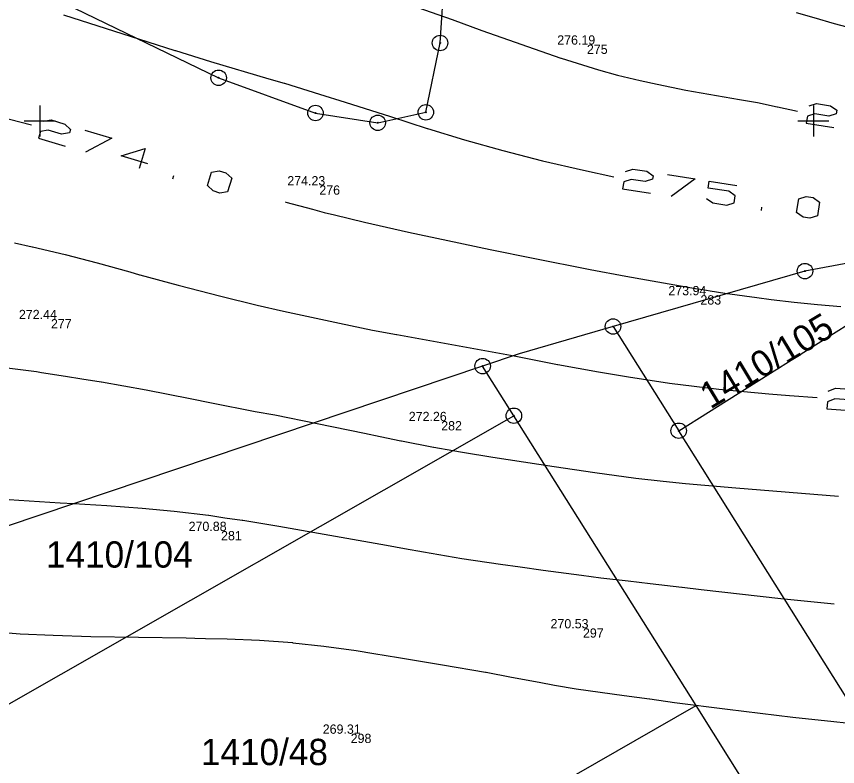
# Model space of a CAD drawing. Extents: x -771260 to -770828, y -1053564 to -1052811.
# Drawn here: x -771201.5 to -771148.4, y -1053191.7 to -1053143.2 of the extents above; entities that cross this region are included whole.
import ezdxf

# ---------------------------------------------------------------- set-up
doc = ezdxf.new("R2010")
doc.units = 0
for name, color, linetype in [('14_8_2023_krizky', 7, 'Continuous'), ('25_3_2019_krizky_JTSK', 7, 'Continuous'), ('25_3_2019_vrstevnice_interval_po_1m', 7, 'Continuous'), ('25_3_2019_zamereny_bod', 7, 'Continuous'), ('25_3_2019_zamereny_bod_cislo', 7, 'Continuous'), ('25_3_2019_zamereny_bod_vyska', 7, 'Continuous'), ('Default', 7, 'Continuous'), ('DKM_Hranice parcel', 7, 'Continuous'), ('DKM_Parcelní čísla', 7, 'Continuous'), ('DKM_Značky bodu BP', 7, 'Continuous')]:
    doc.layers.add(name, color=color, linetype=linetype)

# ---------------------------------------------------------------- blocks, each defined once
blk = doc.blocks.new('POINT_DISPLAY')
at = {"layer": 'Default'}
blk.add_line((0, 0), (0, 0), dxfattribs=at)
blk = doc.blocks.new('KRIZEK')
at = {"layer": '25_3_2019_krizky_JTSK'}
for p, q in [((0, 10), (0, -10)), ((-10, 0), (10, 0))]:
    blk.add_line(p, q, dxfattribs=at)

msp = doc.modelspace()

# ---------------------------------------------------------------- linework, layer by layer
at = {"layer": '25_3_2019_vrstevnice_interval_po_1m'}
for points in [[(-771176.495, -1053142.335), (-771173.356, -1053143.447), (-771171.429, -1053144.145), (-771166.321, -1053145.933), (-771166.299, -1053145.94), (-771163.9, -1053146.699), (-771163.882, -1053146.705), (-771162.655, -1053147.03), (-771161.203, -1053147.394), (-771160.11, -1053147.627), (-771158.237, -1053148), (-771154.77, -1053148.605), (-771153.622, -1053148.815), (-771152.336, -1053149.082), (-771152.333, -1053149.082), (-771151.031, -1053149.364)], [(-771198.459, -1053143.131), (-771193.008, -1053144.884), (-771191.261, -1053145.439), (-771191.218, -1053145.452), (-771188.954, -1053146.148), (-771185.193, -1053147.279), (-771184.207, -1053147.564), (-771184.193, -1053147.568), (-771181.911, -1053148.263), (-771180.257, -1053148.792), (-771177.326, -1053149.711), (-771174.969, -1053150.485), (-771174.946, -1053150.492), (-771172.54, -1053151.23), (-771170.074, -1053151.921), (-771167.509, -1053152.578), (-771164.865, -1053153.193), (-771162.899, -1053153.607)], [(-771151.125, -1053142.985), (-771149.981, -1053143.315), (-771148.658, -1053143.697), (-771147.434, -1053144.028), (-771144.859, -1053144.682), (-771143.67, -1053144.965), (-771143.652, -1053144.97), (-771142.265, -1053145.32), (-771139.641, -1053145.912), (-771138.851, -1053146.062), (-771138.315, -1053146.174), (-771136.98, -1053146.418), (-771136.977, -1053146.419), (-771135.671, -1053146.639), (-771134.241, -1053146.845)], [(-771173.356, -1053143.447), (-771173.356, -1053143.447)], [(-771148.658, -1053143.697), (-771148.658, -1053143.697)], [(-771171.429, -1053144.145), (-771171.429, -1053144.145)], [(-771193.008, -1053144.884), (-771193.008, -1053144.884)], [(-771191.218, -1053145.452), (-771191.218, -1053145.452)], [(-771166.321, -1053145.933), (-771166.321, -1053145.933)], [(-771188.954, -1053146.148), (-771188.954, -1053146.148)], [(-771163.882, -1053146.705), (-771163.882, -1053146.705)], [(-771162.655, -1053147.03), (-771162.655, -1053147.03)], [(-771185.193, -1053147.279), (-771185.193, -1053147.279)], [(-771184.193, -1053147.568), (-771184.193, -1053147.568)], [(-771161.203, -1053147.394), (-771161.203, -1053147.394)], [(-771160.11, -1053147.627), (-771160.11, -1053147.627)], [(-771158.237, -1053148), (-771158.237, -1053148)], [(-771181.911, -1053148.263), (-771181.911, -1053148.263)], [(-771154.77, -1053148.605), (-771154.77, -1053148.605)], [(-771180.257, -1053148.792), (-771180.257, -1053148.792)], [(-771153.622, -1053148.815), (-771153.622, -1053148.815)], [(-771152.336, -1053149.082), (-771152.336, -1053149.082)], [(-771150.287, -1053149.024), (-771149.803, -1053148.872), (-771148.906, -1053149.016), (-771148.494, -1053149.312), (-771148.53, -1053149.536), (-771149.014, -1053149.688), (-771149.91, -1053149.544), (-771150.395, -1053149.696), (-771150.467, -1053150.144), (-771148.674, -1053150.432)], [(-771202.635, -1053149.719), (-771200.54, -1053150.257)], [(-771199.757, -1053150.02), (-771199.256, -1053149.934), (-771198.388, -1053150.198), (-771198.019, -1053150.547), (-771198.085, -1053150.764), (-771198.585, -1053150.849), (-771199.454, -1053150.586), (-771199.954, -1053150.672), (-771200.086, -1053151.106), (-771198.348, -1053151.632)], [(-771177.326, -1053149.711), (-771177.326, -1053149.711)], [(-771197.085, -1053150.593), (-771195.347, -1053151.119), (-771197.045, -1053152.027)], [(-771174.969, -1053150.485), (-771174.969, -1053150.485)], [(-771172.54, -1053151.23), (-771172.54, -1053151.23)], [(-771193.004, -1053152.778), (-771194.742, -1053152.251), (-771193.176, -1053151.778), (-771193.57, -1053153.081)], [(-771170.074, -1053151.921), (-771170.074, -1053151.921)], [(-771167.509, -1053152.578), (-771167.509, -1053152.578)], [(-771188.793, -1053154.529), (-771189.161, -1053154.18), (-771188.898, -1053153.311), (-771188.398, -1053153.226), (-771187.963, -1053153.357), (-771187.595, -1053153.706), (-771187.858, -1053154.575), (-771188.358, -1053154.66), (-771188.793, -1053154.529)], [(-771164.865, -1053153.193), (-771164.865, -1053153.193)], [(-771162.156, -1053153.265), (-771161.672, -1053153.111), (-771160.775, -1053153.253), (-771160.362, -1053153.547), (-771160.398, -1053153.772), (-771160.881, -1053153.925), (-771161.778, -1053153.784), (-771162.262, -1053153.937), (-771162.332, -1053154.386), (-771160.539, -1053154.668)], [(-771191.399, -1053153.739), (-771191.333, -1053153.522)], [(-771159.43, -1053153.465), (-771157.637, -1053153.747), (-771159.194, -1053154.88)], [(-771156.917, -1053155.009), (-771156.504, -1053155.304), (-771155.607, -1053155.445), (-771155.124, -1053155.292), (-771155.053, -1053154.844), (-771155.466, -1053154.549), (-771156.811, -1053154.337), (-771156.74, -1053153.888), (-771154.947, -1053154.171)], [(-771150.675, -1053156.223), (-771151.088, -1053155.928), (-771150.947, -1053155.031), (-771150.464, -1053154.877), (-771150.015, -1053154.948), (-771149.602, -1053155.243), (-771149.743, -1053156.14), (-771150.227, -1053156.293), (-771150.675, -1053156.223)], [(-771184.111, -1053155.236), (-771184.111, -1053155.236)], [(-771184.111, -1053155.236), (-771184.086, -1053155.243), (-771182.368, -1053155.706), (-771181.615, -1053155.909), (-771180.948, -1053156.07), (-771179.002, -1053156.54), (-771176.166, -1053157.182), (-771173.622, -1053157.74), (-771170.887, -1053158.318), (-771168.122, -1053158.88), (-771164.439, -1053159.597), (-771162.119, -1053160.03), (-771160.792, -1053160.264), (-771157.495, -1053160.846), (-771157.479, -1053160.849), (-771157.152, -1053160.901), (-771156.683, -1053160.975), (-771155.723, -1053161.128), (-771153.65, -1053161.425), (-771152.741, -1053161.538), (-771151.241, -1053161.708), (-771149.737, -1053161.858), (-771148.227, -1053161.991)], [(-771181.615, -1053155.909), (-771181.615, -1053155.909)], [(-771153.365, -1053155.799), (-771153.33, -1053155.574)], [(-771179.002, -1053156.54), (-771179.002, -1053156.54)], [(-771176.166, -1053157.182), (-771176.166, -1053157.182)], [(-771201.627, -1053157.886), (-771200.482, -1053158.129), (-771200.47, -1053158.132), (-771198.357, -1053158.641), (-771196.286, -1053159.182), (-771194.18, -1053159.761), (-771193.55, -1053159.942), (-771193.525, -1053159.948), (-771191.056, -1053160.616), (-771188.304, -1053161.329), (-771185.955, -1053161.909), (-771184.242, -1053162.296), (-771184.241, -1053162.297), (-771180.621, -1053163.082), (-771178.486, -1053163.517), (-771176.95, -1053163.807), (-771176.932, -1053163.811), (-771172.176, -1053164.663), (-771169.342, -1053165.193), (-771166.539, -1053165.738), (-771166.511, -1053165.743), (-771163.882, -1053166.232), (-771161.945, -1053166.554), (-771159.308, -1053166.951), (-771159.306, -1053166.951), (-771157.713, -1053167.156), (-771156.108, -1053167.335), (-771152.88, -1053167.638), (-771151.542, -1053167.743), (-771149.761, -1053167.882)], [(-771200.47, -1053158.132), (-771200.47, -1053158.132)], [(-771173.622, -1053157.74), (-771173.622, -1053157.74)], [(-771198.357, -1053158.641), (-771198.357, -1053158.641)], [(-771170.887, -1053158.318), (-771170.887, -1053158.318)], [(-771196.286, -1053159.182), (-771196.286, -1053159.182)], [(-771168.122, -1053158.88), (-771168.122, -1053158.88)], [(-771194.18, -1053159.761), (-771194.18, -1053159.761)], [(-771164.439, -1053159.597), (-771164.439, -1053159.597)], [(-771193.55, -1053159.942), (-771193.55, -1053159.942)], [(-771162.119, -1053160.03), (-771162.119, -1053160.03)], [(-771191.056, -1053160.616), (-771191.056, -1053160.616)], [(-771188.304, -1053161.329), (-771188.304, -1053161.329)], [(-771157.479, -1053160.849), (-771157.479, -1053160.849)], [(-771155.723, -1053161.128), (-771155.723, -1053161.128)], [(-771153.65, -1053161.425), (-771153.65, -1053161.425)], [(-771152.741, -1053161.538), (-771152.741, -1053161.538)], [(-771151.241, -1053161.708), (-771151.241, -1053161.708)], [(-771149.737, -1053161.858), (-771149.737, -1053161.858)], [(-771185.955, -1053161.909), (-771185.955, -1053161.909)], [(-771184.242, -1053162.296), (-771184.242, -1053162.296)], [(-771180.621, -1053163.082), (-771180.621, -1053163.082)], [(-771178.486, -1053163.517), (-771178.486, -1053163.517)], [(-771176.932, -1053163.811), (-771176.932, -1053163.811)], [(-771172.176, -1053164.663), (-771172.176, -1053164.663)], [(-771169.342, -1053165.193), (-771169.342, -1053165.193)], [(-771202.103, -1053165.959), (-771200.206, -1053166.21), (-771199.884, -1053166.259), (-771198.331, -1053166.492), (-771197.273, -1053166.668), (-771196.025, -1053166.866), (-771195.999, -1053166.87), (-771193.114, -1053167.395), (-771190.272, -1053167.954), (-771188.908, -1053168.235), (-771186.085, -1053168.779), (-771186.084, -1053168.779), (-771184.812, -1053169.009), (-771182.065, -1053169.554), (-771179.002, -1053170.195), (-771178.004, -1053170.411), (-771176.655, -1053170.687), (-771176.627, -1053170.692), (-771174.544, -1053171.094), (-771174.543, -1053171.094), (-771173.303, -1053171.311), (-771172.685, -1053171.412), (-771170.712, -1053171.731), (-771166.762, -1053172.342), (-771164.122, -1053172.73), (-771161.472, -1053173.09), (-771161.47, -1053173.09), (-771159.722, -1053173.285), (-771158.259, -1053173.437), (-771155.025, -1053173.722), (-771148.389, -1053174.265)], [(-771166.539, -1053165.738), (-771166.539, -1053165.738)], [(-771200.206, -1053166.21), (-771200.206, -1053166.21)], [(-771198.331, -1053166.492), (-771198.331, -1053166.492)], [(-771197.273, -1053166.668), (-771197.273, -1053166.668)], [(-771163.882, -1053166.232), (-771163.882, -1053166.232)], [(-771161.945, -1053166.554), (-771161.945, -1053166.554)], [(-771195.999, -1053166.87), (-771195.999, -1053166.87)], [(-771159.308, -1053166.951), (-771159.308, -1053166.951)], [(-771157.713, -1053167.156), (-771157.713, -1053167.156)], [(-771193.114, -1053167.395), (-771193.114, -1053167.395)], [(-771156.108, -1053167.335), (-771156.108, -1053167.335)], [(-771152.88, -1053167.638), (-771152.88, -1053167.638)], [(-771149.05, -1053167.477), (-771148.581, -1053167.283), (-771147.676, -1053167.347), (-771147.239, -1053167.605), (-771147.255, -1053167.832), (-771147.724, -1053168.026), (-771148.629, -1053167.962), (-771149.098, -1053168.156), (-771149.13, -1053168.609), (-771147.319, -1053168.737)], [(-771190.272, -1053167.954), (-771190.272, -1053167.954)], [(-771188.908, -1053168.235), (-771188.908, -1053168.235)], [(-771186.085, -1053168.779), (-771186.085, -1053168.779)], [(-771184.812, -1053169.009), (-771184.812, -1053169.009)], [(-771182.065, -1053169.554), (-771182.065, -1053169.554)], [(-771179.002, -1053170.195), (-771179.002, -1053170.195)], [(-771178.004, -1053170.411), (-771178.004, -1053170.411)], [(-771176.655, -1053170.687), (-771176.655, -1053170.687)], [(-771174.544, -1053171.094), (-771174.544, -1053171.094)], [(-771173.303, -1053171.311), (-771173.303, -1053171.311)], [(-771170.712, -1053171.731), (-771170.712, -1053171.731)], [(-771166.762, -1053172.342), (-771166.762, -1053172.342)], [(-771164.122, -1053172.73), (-771164.122, -1053172.73)], [(-771161.472, -1053173.09), (-771161.472, -1053173.09)], [(-771159.722, -1053173.285), (-771159.722, -1053173.285)], [(-771158.259, -1053173.437), (-771158.259, -1053173.437)], [(-771155.025, -1053173.722), (-771155.025, -1053173.722)], [(-771202.631, -1053174.442), (-771201.343, -1053174.521), (-771198.689, -1053174.685), (-771197.802, -1053174.732), (-771195.666, -1053174.866), (-771193.386, -1053175.038), (-771191.318, -1053175.229), (-771189.102, -1053175.491), (-771189.077, -1053175.494), (-771188.038, -1053175.65), (-771188.037, -1053175.651), (-771186.908, -1053175.807), (-771186.879, -1053175.812), (-771184.542, -1053176.201), (-771177.593, -1053177.422), (-771176.436, -1053177.635), (-771175.199, -1053177.862), (-771172.713, -1053178.281), (-771170.216, -1053178.662), (-771168.963, -1053178.837), (-771167.475, -1053179.034), (-771165, -1053179.361), (-771163.745, -1053179.537), (-771163.742, -1053179.537), (-771161.984, -1053179.74), (-771160.543, -1053179.916), (-771158.515, -1053180.137), (-771158.479, -1053180.142), (-771157.253, -1053180.293), (-771152.101, -1053180.869), (-771148.661, -1053181.229)], [(-771198.689, -1053174.685), (-771198.689, -1053174.685)], [(-771197.802, -1053174.732), (-771197.802, -1053174.732)], [(-771195.666, -1053174.866), (-771195.666, -1053174.866)], [(-771193.386, -1053175.038), (-771193.386, -1053175.038)], [(-771191.318, -1053175.229), (-771191.318, -1053175.229)], [(-771189.077, -1053175.494), (-771189.077, -1053175.494)], [(-771188.038, -1053175.65), (-771188.038, -1053175.65)], [(-771186.908, -1053175.807), (-771186.908, -1053175.807)], [(-771184.542, -1053176.201), (-771184.542, -1053176.201)], [(-771177.593, -1053177.422), (-771177.593, -1053177.422)], [(-771175.199, -1053177.862), (-771175.199, -1053177.862)], [(-771172.713, -1053178.281), (-771172.713, -1053178.281)], [(-771170.216, -1053178.662), (-771170.216, -1053178.662)], [(-771168.963, -1053178.837), (-771168.963, -1053178.837)], [(-771165, -1053179.361), (-771165, -1053179.361)], [(-771163.745, -1053179.537), (-771163.745, -1053179.537)], [(-771161.984, -1053179.74), (-771161.984, -1053179.74)], [(-771160.543, -1053179.916), (-771160.543, -1053179.916)], [(-771158.515, -1053180.137), (-771158.515, -1053180.137)], [(-771157.253, -1053180.293), (-771157.253, -1053180.293)], [(-771152.101, -1053180.869), (-771152.101, -1053180.869)], [(-771202.037, -1053183.098), (-771201.274, -1053183.152), (-771199.14, -1053183.256), (-771196.692, -1053183.328), (-771190.544, -1053183.428), (-771189.972, -1053183.437), (-771189.29, -1053183.461), (-771187.893, -1053183.491), (-771185.792, -1053183.579), (-771183.67, -1053183.731), (-771183.65, -1053183.732), (-771181.632, -1053183.953), (-771179.552, -1053184.238), (-771178.402, -1053184.425), (-771176.808, -1053184.684), (-771173.981, -1053185.156), (-771171.185, -1053185.643), (-771171.155, -1053185.648), (-771169.521, -1053185.96), (-771167.727, -1053186.283), (-771166.73, -1053186.475), (-771165.335, -1053186.714), (-771165.333, -1053186.715), (-771162.225, -1053187.155), (-771160.603, -1053187.369), (-771160.575, -1053187.373), (-771158.973, -1053187.596), (-771155.552, -1053188.039), (-771151.324, -1053188.541), (-771148.69, -1053188.836), (-771147.096, -1053189.004)], [(-771201.274, -1053183.152), (-771201.274, -1053183.152)], [(-771199.14, -1053183.256), (-771199.14, -1053183.256)], [(-771196.692, -1053183.328), (-771196.692, -1053183.328)], [(-771189.972, -1053183.437), (-771189.972, -1053183.437)], [(-771189.29, -1053183.461), (-771189.29, -1053183.461)], [(-771187.893, -1053183.491), (-771187.893, -1053183.491)], [(-771185.792, -1053183.579), (-771185.792, -1053183.579)], [(-771183.65, -1053183.732), (-771183.65, -1053183.732)], [(-771181.632, -1053183.953), (-771181.632, -1053183.953)], [(-771179.552, -1053184.238), (-771179.552, -1053184.238)], [(-771176.808, -1053184.684), (-771176.808, -1053184.684)], [(-771173.981, -1053185.156), (-771173.981, -1053185.156)], [(-771171.185, -1053185.643), (-771171.185, -1053185.643)], [(-771169.521, -1053185.96), (-771169.521, -1053185.96)], [(-771167.727, -1053186.283), (-771167.727, -1053186.283)], [(-771166.73, -1053186.475), (-771166.73, -1053186.475)], [(-771165.333, -1053186.715), (-771165.333, -1053186.715)], [(-771162.225, -1053187.155), (-771162.225, -1053187.155)], [(-771160.575, -1053187.373), (-771160.575, -1053187.373)], [(-771158.973, -1053187.596), (-771158.973, -1053187.596)], [(-771155.552, -1053188.039), (-771155.552, -1053188.039)], [(-771151.324, -1053188.541), (-771151.324, -1053188.541)], [(-771148.69, -1053188.836), (-771148.69, -1053188.836)], [(-771148.69, -1053188.836), (-771148.69, -1053188.836)]]:
    msp.add_lwpolyline(points, dxfattribs=at)
at = {"layer": 'DKM_Hranice parcel'}
for p, q in [((-771158.71, -1053170.03), (-771138.1, -1053157.08)), ((-771162.95, -1053163.29), (-771158.71, -1053170.03)), ((-771169.36, -1053169.06), (-771171.38, -1053165.85)), ((-771212.03, -1053193.43), (-771169.36, -1053169.06)), ((-771157.58, -1053187.8), (-771169.36, -1053169.06)), ((-771147.01, -1053188.66), (-771158.71, -1053170.03)), ((-771200.65, -1053212.45), (-771157.58, -1053187.8)), ((-771145.98, -1053206.27), (-771157.58, -1053187.8))]:
    msp.add_line(p, q, dxfattribs=at)
for points in [[(-771234.22, -1053144), (-771211.57, -1053140.91), (-771205.43, -1053140.71), (-771198.42, -1053142.38), (-771188.44, -1053147.21), (-771182.18, -1053149.49), (-771178.16, -1053150.12), (-771175.05, -1053149.44), (-771174.13, -1053144.96), (-771173.57, -1053136.47), (-771171.38, -1053112.57), (-771169.97, -1053090.2), (-771169.61, -1053079.22)], [(-771138.1, -1053157.08), (-771142.45, -1053158.2), (-771150.55, -1053159.71), (-771162.95, -1053163.29)], [(-771162.95, -1053163.29), (-771169.02, -1053165.05), (-771171.38, -1053165.85)], [(-771171.38, -1053165.85), (-771204.36, -1053176.95), (-771217.3, -1053182.82)]]:
    msp.add_lwpolyline(points, dxfattribs=at)
at = {"layer": 'DKM_Značky bodu BP'}
for centre, radius in [((-771174.13, -1053144.96), 0.5), ((-771174.13, -1053144.96), 0.0303), ((-771188.44, -1053147.21), 0.5), ((-771188.44, -1053147.21), 0.0303), ((-771182.18, -1053149.49), 0.5), ((-771175.05, -1053149.44), 0.5), ((-771182.18, -1053149.49), 0.0303), ((-771178.16, -1053150.12), 0.5), ((-771175.05, -1053149.44), 0.0303), ((-771178.16, -1053150.12), 0.0303), ((-771150.55, -1053159.71), 0.5), ((-771150.55, -1053159.71), 0.0303), ((-771162.95, -1053163.29), 0.5), ((-771162.95, -1053163.29), 0.0303), ((-771171.38, -1053165.85), 0.5), ((-771171.38, -1053165.85), 0.0303), ((-771169.36, -1053169.06), 0.5), ((-771169.36, -1053169.06), 0.0303), ((-771158.71, -1053170.03), 0.5), ((-771158.71, -1053170.03), 0.0303)]:
    msp.add_circle(centre, radius, dxfattribs=at)

# ---------------------------------------------------------------- block references
at = {"layer": '14_8_2023_krizky', "xscale": 0.1, "yscale": 0.10000000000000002}
for p in [(-771200, -1053150), (-771150, -1053150)]:
    msp.add_blockref('KRIZEK', p, dxfattribs=at)
at = {"layer": '25_3_2019_zamereny_bod', "xscale": 0.1, "yscale": 0.10000000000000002}
for p in [(-771164.639, -1053145.066), (-771181.931, -1053154.169), (-771157.303, -1053161.27), (-771199.276, -1053162.815), (-771174.055, -1053169.408), (-771188.282, -1053176.512), (-771164.895, -1053182.807), (-771179.906, -1053189.621)]:
    msp.add_blockref('POINT_DISPLAY', p, dxfattribs=at)

# ---------------------------------------------------------------- texts
at = {"layer": '25_3_2019_zamereny_bod_cislo'}
for s, p in [('275', (-771164.639, -1053145.666)), ('276', (-771181.931, -1053154.769)), ('283', (-771157.303, -1053161.87)), ('277', (-771199.276, -1053163.415)), ('282', (-771174.055, -1053170.008)), ('281', (-771188.282, -1053177.112)), ('297', (-771164.895, -1053183.407)), ('298', (-771179.906, -1053190.221))]:
    msp.add_text(s, height=0.6, dxfattribs=at).set_placement(p)
at = {"layer": '25_3_2019_zamereny_bod_vyska'}
for s, p in [('276.19 ', (-771166.558, -1053145.066)), ('274.23 ', (-771184.001, -1053154.169)), ('273.94 ', (-771159.375, -1053161.27)), ('272.44 ', (-771201.346, -1053162.815)), ('272.26 ', (-771176.153, -1053169.408)), ('270.88 ', (-771190.378, -1053176.512)), ('270.53 ', (-771166.991, -1053182.807)), ('269.31 ', (-771181.711, -1053189.621))]:
    msp.add_text(s, height=0.6, dxfattribs=at).set_placement(p)
at = {"layer": 'DKM_Parcelní čísla'}
msp.add_text('1410/105', height=1.7, rotation=31, dxfattribs=at).set_placement((-771156.662, -1053168.668))
for s, p in [('1410/104', (-771199.6, -1053178.88)), ('1410/48', (-771189.59, -1053191.65))]:
    msp.add_text(s, height=1.7, dxfattribs=at).set_placement(p)

doc.saveas('drawing.dxf')
